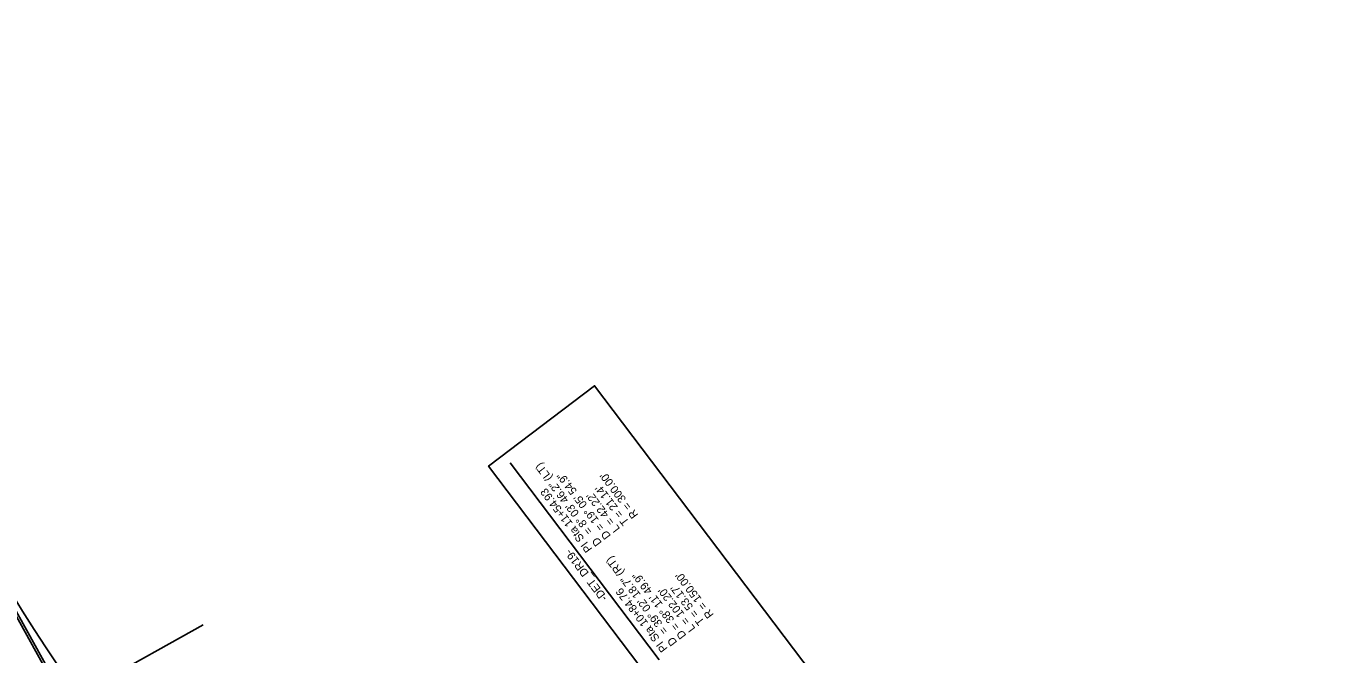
# Model space of a CAD drawing. Extents: x 473658 to 481584, y 489119 to 506230.
# Drawn here: x 476199 to 477333, y 501237 to 501786 of the extents above; entities that cross this region are included whole.
import ezdxf

# ---------------------------------------------------------------- set-up
doc = ezdxf.new("R2010")
doc.units = 0
for name, color, linetype in [('Prop EOT', 7, 'Continuous'), ('Prop Grid Mask', 7, 'Continuous'), ('Prop Horizontal Alignment', 7, 'Continuous'), ('Prop Horizontal Alignment Curve and Spiral Data', 7, 'Continuous'), ('Prop Horizontal Alignment Station Label', 7, 'Continuous'), ('Prop Paved Shoulder', 7, 'Continuous'), ('Scratch_Level_5', 7, 'Continuous')]:
    doc.layers.add(name, color=color, linetype=linetype)

msp = doc.modelspace()

# ---------------------------------------------------------------- linework, layer by layer
at = {"layer": 'Prop EOT'}
msp.add_line((476290.2, 501090.7), (475837.1, 501906.2), dxfattribs=at)
at = {"layer": 'Prop Grid Mask'}
msp.add_lwpolyline([(477240.4, 500559.9), (476603.5, 501401.3), (476696.2, 501471.5), (477333.1, 500630.1)], close=True, dxfattribs=at)
at = {"layer": 'Prop Horizontal Alignment'}
msp.add_arc((478615.6, 502799.6), 2860, 203.8164, 228.2476, dxfattribs=at)
at = {"layer": 'Prop Horizontal Alignment Curve and Spiral Data'}
msp.add_line((476752.6, 501232), (476622.2, 501404.3), dxfattribs=at)
at = {"layer": 'Prop Paved Shoulder'}
msp.add_line((476292, 501091.7), (475838.8, 501907.1), dxfattribs=at)
at = {"layer": 'Scratch_Level_5'}
msp.add_line((476188.8, 501170.8), (476353.8, 501262.5), dxfattribs=at)

# ---------------------------------------------------------------- texts
at = {"layer": 'Prop Horizontal Alignment Curve and Spiral Data'}
for s, p in [('= 8%%d 03\' 46.2" (LT)', (476694.8, 501344.6)), ('D = 19%%d 05\' 54.9"', (476710.7, 501340.5)), ("R = 300.00'", (476734.6, 501358.7)), ('PI Sta 11+54.93', (476694.4, 501329)), ("T = 21.14'", (476726.7, 501352.6)), ("L = 42.22'", (476718.7, 501346.6)), ('D', (476702.8, 501334.5)), ('= 39%%d 02\' 18.7" (RT)', (476760.7, 501257.5)), ('D = 38%%d 11\' 49.9"', (476776.7, 501253.4)), ("R = 150.00'", (476800.6, 501271.5)), ('PI Sta 10+84.76', (476760.3, 501241.9)), ("L = 102.20'", (476784.6, 501259.5)), ("T = 53.17'", (476792.6, 501265.5)), ('D', (476768.7, 501247.4))]:
    msp.add_text(s, height=7, rotation=127.1236, dxfattribs=at).set_placement(p)
at = {"layer": 'Prop Horizontal Alignment Station Label'}
msp.add_text('-DET_DR19-', height=7, rotation=127.1236, dxfattribs=at).set_placement((476707.8, 501286.4))

doc.saveas('drawing.dxf')
